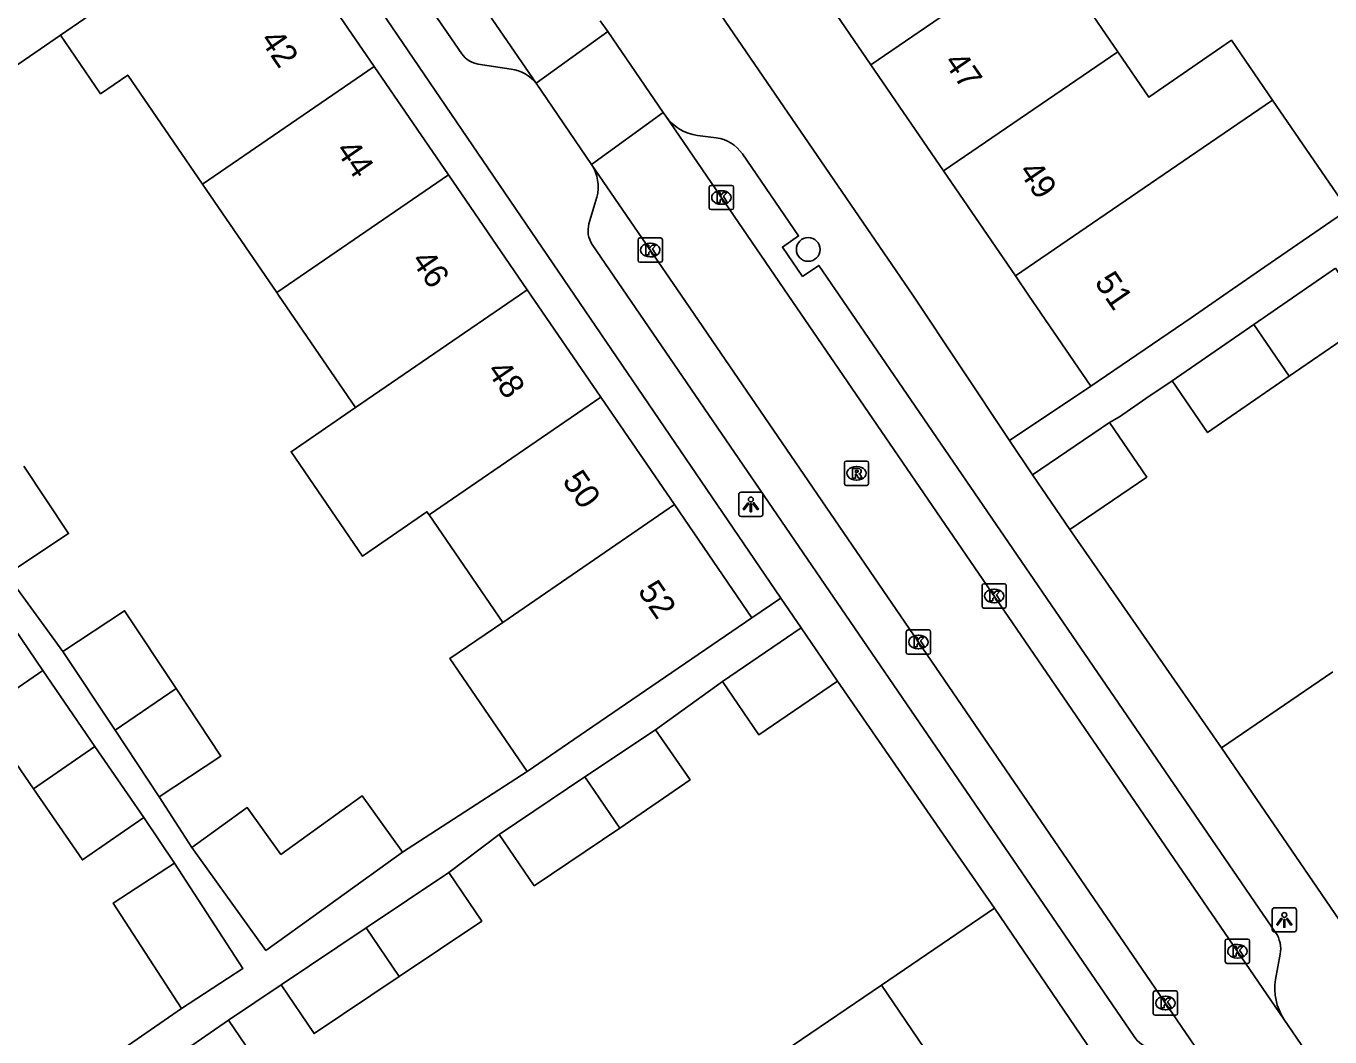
# Model space of a CAD drawing. Extents: x 157466 to 158888, y 383063 to 384677.
# Drawn here: x 158174.5 to 158228.2, y 383719.4 to 383761.1 of the extents above; entities that cross this region are included whole.
import ezdxf

# ---------------------------------------------------------------- set-up
doc = ezdxf.new("R2010")
doc.units = 0
for name, color, linetype in [('IMGEO_Boom', 7, 'Continuous'), ('IMGEO_Kolk', 7, 'Continuous'), ('IMGEO_Lichtpunt', 7, 'Continuous'), ('IMGEO_Muur', 7, 'Continuous'), ('IMGEO_Pand', 7, 'Continuous'), ('IMGEO_Pand_nummerreeks', 7, 'Continuous'), ('IMGEO_Rijbaan_lokaal_open', 7, 'Continuous'), ('IMGEO_Rioolput', 7, 'Continuous'), ('IMGEO_Voetpad_open', 7, 'Continuous')]:
    doc.layers.add(name, color=color, linetype=linetype)

msp = doc.modelspace()

# ---------------------------------------------------------------- linework, layer by layer
at = {"layer": 'IMGEO_Boom'}
msp.add_circle((158206.748, 383751.883), 0.489, dxfattribs=at)
at = {"layer": 'IMGEO_Kolk'}
for p, q in [((158202.669, 383753.595), (158202.669, 383754.447)), ((158202.744, 383754.521), (158203.596, 383754.521)), ((158203.157, 383754.301), (158203.182, 383754.301)), ((158203.67, 383754.447), (158203.67, 383753.595)), ((158203.18, 383753.741), (158203.155, 383753.741)), ((158203.596, 383753.521), (158202.744, 383753.521)), ((158199.737, 383751.428), (158199.737, 383752.28)), ((158199.812, 383752.354), (158200.664, 383752.354)), ((158200.225, 383752.134), (158200.25, 383752.134)), ((158200.738, 383752.28), (158200.738, 383751.428)), ((158200.248, 383751.574), (158200.223, 383751.574)), ((158200.664, 383751.354), (158199.812, 383751.354)), ((158213.984, 383738.11), (158214.836, 383738.11)), ((158213.909, 383737.184), (158213.909, 383738.036)), ((158214.397, 383737.89), (158214.422, 383737.89)), ((158214.91, 383738.036), (158214.91, 383737.184)), ((158214.836, 383737.11), (158213.984, 383737.11)), ((158214.42, 383737.33), (158214.395, 383737.33)), ((158210.788, 383735.283), (158210.788, 383736.135)), ((158210.863, 383736.209), (158211.715, 383736.209)), ((158211.276, 383735.989), (158211.301, 383735.989)), ((158211.789, 383736.135), (158211.789, 383735.283)), ((158211.299, 383735.429), (158211.274, 383735.429)), ((158211.715, 383735.209), (158210.863, 383735.209)), ((158223.932, 383722.549), (158223.932, 383723.401)), ((158224.007, 383723.475), (158224.859, 383723.475)), ((158224.42, 383723.255), (158224.445, 383723.255)), ((158224.933, 383723.401), (158224.933, 383722.549)), ((158224.859, 383722.475), (158224.007, 383722.475)), ((158224.443, 383722.695), (158224.418, 383722.695)), ((158220.967, 383720.413), (158220.967, 383721.265)), ((158221.042, 383721.339), (158221.894, 383721.339)), ((158221.455, 383721.119), (158221.48, 383721.119)), ((158221.968, 383721.265), (158221.968, 383720.413)), ((158221.894, 383720.339), (158221.042, 383720.339)), ((158221.478, 383720.559), (158221.453, 383720.559))]:
    msp.add_line(p, q, dxfattribs=at)
for points in [[(158202.669, 383753.595), (158202.669, 383754.447)], [(158202.744, 383754.521), (158203.596, 383754.521)], [(158202.99, 383754.221), (158203.113, 383754.221), (158203.113, 383754.07), (158203.243, 383754.221), (158203.407, 383754.221), (158203.261, 383754.07), (158203.414, 383753.821), (158203.262, 383753.821), (158203.177, 383753.985), (158203.113, 383753.918), (158203.113, 383753.821), (158202.99, 383753.821), (158202.99, 383754.221)], [(158203.67, 383754.447), (158203.67, 383753.595)], [(158203.596, 383753.521), (158202.744, 383753.521)], [(158199.737, 383751.428), (158199.737, 383752.28)], [(158199.812, 383752.354), (158200.664, 383752.354)], [(158200.058, 383752.054), (158200.181, 383752.054), (158200.181, 383751.903), (158200.311, 383752.054), (158200.475, 383752.054), (158200.329, 383751.903), (158200.482, 383751.654), (158200.33, 383751.654), (158200.245, 383751.818), (158200.181, 383751.751), (158200.181, 383751.654), (158200.058, 383751.654), (158200.058, 383752.054)], [(158200.738, 383752.28), (158200.738, 383751.428)], [(158200.664, 383751.354), (158199.812, 383751.354)], [(158213.984, 383738.11), (158214.836, 383738.11)], [(158213.909, 383737.184), (158213.909, 383738.036)], [(158214.23, 383737.81), (158214.353, 383737.81), (158214.353, 383737.659), (158214.483, 383737.81), (158214.647, 383737.81), (158214.501, 383737.659), (158214.654, 383737.41), (158214.502, 383737.41), (158214.417, 383737.574), (158214.353, 383737.507), (158214.353, 383737.41), (158214.23, 383737.41), (158214.23, 383737.81)], [(158214.91, 383738.036), (158214.91, 383737.184)], [(158214.836, 383737.11), (158213.984, 383737.11)], [(158210.788, 383735.283), (158210.788, 383736.135)], [(158210.863, 383736.209), (158211.715, 383736.209)], [(158211.109, 383735.909), (158211.232, 383735.909), (158211.232, 383735.758), (158211.362, 383735.909), (158211.526, 383735.909), (158211.38, 383735.758), (158211.533, 383735.509), (158211.381, 383735.509), (158211.296, 383735.673), (158211.232, 383735.606), (158211.232, 383735.509), (158211.109, 383735.509), (158211.109, 383735.909)], [(158211.789, 383736.135), (158211.789, 383735.283)], [(158211.715, 383735.209), (158210.863, 383735.209)], [(158223.932, 383722.549), (158223.932, 383723.401)], [(158224.007, 383723.475), (158224.859, 383723.475)], [(158224.253, 383723.175), (158224.376, 383723.175), (158224.376, 383723.024), (158224.506, 383723.175), (158224.67, 383723.175), (158224.524, 383723.024), (158224.677, 383722.775), (158224.525, 383722.775), (158224.44, 383722.939), (158224.376, 383722.872), (158224.376, 383722.775), (158224.253, 383722.775), (158224.253, 383723.175)], [(158224.933, 383723.401), (158224.933, 383722.549)], [(158224.859, 383722.475), (158224.007, 383722.475)], [(158220.967, 383720.413), (158220.967, 383721.265)], [(158221.042, 383721.339), (158221.894, 383721.339)], [(158221.288, 383721.039), (158221.411, 383721.039), (158221.411, 383720.888), (158221.541, 383721.039), (158221.705, 383721.039), (158221.559, 383720.888), (158221.712, 383720.639), (158221.56, 383720.639), (158221.475, 383720.803), (158221.411, 383720.736), (158221.411, 383720.639), (158221.288, 383720.639), (158221.288, 383721.039)], [(158221.968, 383721.265), (158221.968, 383720.413)], [(158221.894, 383720.339), (158221.042, 383720.339)]]:
    msp.add_lwpolyline(points, dxfattribs=at)
for centre, start, end in [((158202.746, 383754.445), 91.552, 178.448), ((158202.746, 383754.445), 91.552, 178.448), ((158203.594, 383754.445), 1.552, 88.448), ((158203.594, 383754.445), 1.552, 88.448), ((158202.746, 383753.597), 181.552, 268.448), ((158202.746, 383753.597), 181.552, 268.448), ((158203.594, 383753.597), 271.552, 358.448), ((158203.594, 383753.597), 271.552, 358.448), ((158199.814, 383752.278), 91.552, 178.448), ((158199.814, 383752.278), 91.552, 178.448), ((158200.662, 383752.278), 1.552, 88.448), ((158200.662, 383752.278), 1.552, 88.448), ((158199.814, 383751.43), 181.552, 268.448), ((158199.814, 383751.43), 181.552, 268.448), ((158200.662, 383751.43), 271.552, 358.448), ((158200.662, 383751.43), 271.552, 358.448), ((158213.986, 383738.034), 91.552, 178.448), ((158213.986, 383738.034), 91.552, 178.448), ((158214.834, 383738.034), 1.552, 88.448), ((158214.834, 383738.034), 1.552, 88.448), ((158213.986, 383737.186), 181.552, 268.448), ((158213.986, 383737.186), 181.552, 268.448), ((158214.834, 383737.186), 271.552, 358.448), ((158214.834, 383737.186), 271.552, 358.448), ((158210.865, 383736.133), 91.552, 178.448), ((158210.865, 383736.133), 91.552, 178.448), ((158211.713, 383736.133), 1.552, 88.448), ((158211.713, 383736.133), 1.552, 88.448), ((158210.865, 383735.285), 181.552, 268.448), ((158210.865, 383735.285), 181.552, 268.448), ((158211.713, 383735.285), 271.552, 358.448), ((158211.713, 383735.285), 271.552, 358.448), ((158224.009, 383723.399), 91.552, 178.448), ((158224.009, 383723.399), 91.552, 178.448), ((158224.857, 383723.399), 1.552, 88.448), ((158224.857, 383723.399), 1.552, 88.448), ((158224.009, 383722.551), 181.552, 268.448), ((158224.009, 383722.551), 181.552, 268.448), ((158224.857, 383722.551), 271.552, 358.448), ((158224.857, 383722.551), 271.552, 358.448), ((158221.044, 383721.263), 91.552, 178.448), ((158221.044, 383721.263), 91.552, 178.448), ((158221.892, 383721.263), 1.552, 88.448), ((158221.892, 383721.263), 1.552, 88.448), ((158221.044, 383720.415), 181.552, 268.448), ((158221.044, 383720.415), 181.552, 268.448), ((158221.892, 383720.415), 271.552, 358.448), ((158221.892, 383720.415), 271.552, 358.448)]:
    msp.add_arc(centre, 0.0765, start, end, dxfattribs=at)
for centre, major_axis, ratio, start_param, end_param in [((158203.156, 383754.021), (-0.387, 0.002), 0.722429, 4.712389, 7.853982), ((158203.181, 383754.021), (-0.39, 0.002), 0.717154, 1.570796, 4.712389), ((158200.224, 383751.854), (-0.387, 0.002), 0.722429, 4.712389, 7.853982), ((158200.249, 383751.854), (-0.39, 0.002), 0.717154, 1.570796, 4.712389), ((158214.396, 383737.61), (-0.387, 0.002), 0.722429, 4.712389, 7.853982), ((158214.421, 383737.61), (-0.39, 0.002), 0.717154, 1.570796, 4.712389), ((158211.275, 383735.709), (-0.387, 0.002), 0.722429, 4.712389, 7.853982), ((158211.3, 383735.709), (-0.39, 0.002), 0.717154, 1.570796, 4.712389), ((158224.419, 383722.975), (-0.387, 0.002), 0.722429, 4.712389, 7.853982), ((158224.444, 383722.975), (-0.39, 0.002), 0.717154, 1.570796, 4.712389), ((158221.454, 383720.839), (-0.387, 0.002), 0.722429, 4.712389, 7.853982), ((158221.479, 383720.839), (-0.39, 0.002), 0.717154, 1.570796, 4.712389)]:
    msp.add_ellipse(centre, major_axis=major_axis, ratio=ratio, start_param=start_param, end_param=end_param, dxfattribs=at)
at = {"layer": 'IMGEO_Lichtpunt'}
for p, q in [((158204.788, 383741.88), (158203.98, 383741.88)), ((158204.788, 383741.88), (158203.98, 383741.88)), ((158203.886, 383741.785), (158203.886, 383740.978)), ((158203.886, 383741.785), (158203.886, 383740.978)), ((158204.882, 383740.978), (158204.882, 383741.785)), ((158204.882, 383740.978), (158204.882, 383741.785)), ((158203.98, 383740.884), (158204.788, 383740.884)), ((158203.98, 383740.884), (158204.788, 383740.884)), ((158225.866, 383724.672), (158225.866, 383723.865)), ((158225.866, 383724.672), (158225.866, 383723.865)), ((158226.768, 383724.767), (158225.96, 383724.767)), ((158226.768, 383724.767), (158225.96, 383724.767)), ((158226.862, 383723.865), (158226.862, 383724.672)), ((158226.862, 383723.865), (158226.862, 383724.672)), ((158225.96, 383723.771), (158226.768, 383723.771)), ((158225.96, 383723.771), (158226.768, 383723.771))]:
    msp.add_line(p, q, dxfattribs=at)
for points in [[(158204.26, 383741.449), (158204.299, 383741.421), (158204.111, 383741.159), (158204.073, 383741.186), (158204.26, 383741.449)], [(158204.362, 383741.401), (158204.409, 383741.401), (158204.409, 383741.079), (158204.362, 383741.079), (158204.362, 383741.401)], [(158204.472, 383741.421), (158204.51, 383741.448), (158204.697, 383741.186), (158204.658, 383741.158), (158204.472, 383741.421)], [(158226.24, 383724.336), (158226.279, 383724.308), (158226.091, 383724.046), (158226.053, 383724.073), (158226.24, 383724.336)], [(158226.342, 383724.288), (158226.389, 383724.288), (158226.389, 383723.966), (158226.342, 383723.966), (158226.342, 383724.288)], [(158226.452, 383724.308), (158226.49, 383724.335), (158226.677, 383724.073), (158226.638, 383724.045), (158226.452, 383724.308)]]:
    msp.add_lwpolyline(points, dxfattribs=at)
for centre in [(158204.385, 383741.583), (158226.365, 383724.47)]:
    msp.add_circle(centre, 0.0994, dxfattribs=at)
for centre, start, end in [((158203.98, 383741.785), 90, 180), ((158203.98, 383741.785), 90, 180), ((158204.788, 383741.785), 0, 90), ((158204.788, 383741.785), 0, 90), ((158203.98, 383740.978), 180, 270), ((158203.98, 383740.978), 180, 270), ((158204.788, 383740.978), 270, 0), ((158204.788, 383740.978), 270, 360), ((158225.96, 383724.672), 90, 180), ((158225.96, 383724.672), 90, 180), ((158226.768, 383724.672), 0, 90), ((158226.768, 383724.672), 0, 90), ((158225.96, 383723.865), 180, 270), ((158225.96, 383723.865), 180, 270), ((158226.768, 383723.865), 270, 0), ((158226.768, 383723.865), 270, 360)]:
    msp.add_arc(centre, 0.0946, start, end, dxfattribs=at)
at = {"layer": 'IMGEO_Muur'}
for points in [[(158222.063, 383733.823), (158223.783, 383731.353)], [(158212.709, 383727.225), (158214.422, 383724.75)]]:
    msp.add_lwpolyline(points, dxfattribs=at)
at = {"layer": 'IMGEO_Pand'}
for points in [[(158216.508, 383764.396), (158209.334, 383759.486)], [(158219.501, 383760.026), (158216.508, 383764.396)], [(158175.939, 383760.709), (158180.833, 383764.065)], [(158180.833, 383764.065), (158182.46, 383761.691), (158185.753, 383763.949), (158188.863, 383759.413)], [(158209.334, 383759.486), (158206.199, 383764.067)], [(158175.939, 383760.709), (158177.586, 383758.297), (158178.707, 383759.066), (158181.791, 383754.566)], [(158219.501, 383760.026), (158220.781, 383758.158), (158224.188, 383760.497), (158225.877, 383758.036)], [(158212.326, 383755.115), (158219.501, 383760.026)], [(158188.863, 383759.413), (158181.791, 383754.566)], [(158188.863, 383759.413), (158191.92, 383754.953)], [(158212.326, 383755.115), (158209.334, 383759.486)], [(158225.877, 383758.036), (158222.464, 383755.701), (158215.286, 383750.789)], [(158228.983, 383753.512), (158225.877, 383758.036)], [(158184.848, 383750.106), (158191.92, 383754.953)], [(158191.92, 383754.953), (158195.167, 383750.218)], [(158215.286, 383750.789), (158212.326, 383755.115)], [(158181.791, 383754.566), (158184.848, 383750.106)], [(158228.983, 383753.512), (158225.569, 383751.168), (158223.877, 383750), (158222.525, 383749.067), (158218.397, 383746.244)], [(158225.108, 383748.791), (158228.476, 383751.106)], [(158226.568, 383746.655), (158229.936, 383748.97), (158228.476, 383751.106)], [(158218.397, 383746.244), (158215.826, 383750), (158215.286, 383750.789)], [(158184.848, 383750.106), (158184.921, 383750), (158188.094, 383745.37)], [(158195.167, 383750.218), (158194.849, 383750), (158188.094, 383745.37)], [(158195.167, 383750.218), (158195.316, 383750), (158198.201, 383745.792)], [(158221.742, 383746.476), (158225.108, 383748.791)], [(158226.568, 383746.655), (158225.108, 383748.791)], [(158221.742, 383746.476), (158223.202, 383744.341), (158226.568, 383746.655)], [(158198.201, 383745.792), (158191.128, 383740.944)], [(158198.201, 383745.792), (158201.232, 383741.371)], [(158188.094, 383745.37), (158185.436, 383743.548), (158188.379, 383739.254), (158191.037, 383741.076), (158191.128, 383740.944)], [(158215.989, 383742.592), (158219.158, 383744.755)], [(158219.158, 383744.755), (158220.694, 383742.504), (158217.525, 383740.341)], [(158173.727, 383738.491), (158176.267, 383740.175), (158174.421, 383742.96)], [(158217.525, 383740.341), (158215.989, 383742.592)], [(158194.158, 383736.522), (158201.232, 383741.371)], [(158201.232, 383741.371), (158204.427, 383736.711)], [(158191.128, 383740.944), (158194.158, 383736.522)], [(158180.702, 383733.797), (158178.578, 383737), (158176.038, 383735.315)], [(158194.158, 383736.522), (158191.984, 383735.035), (158195.169, 383730.379)], [(158195.169, 383730.379), (158197.347, 383731.869), (158200.3, 383733.889), (158204.427, 383736.711)], [(158206.451, 383736.296), (158203.212, 383734.083)], [(158206.451, 383736.296), (158207.95, 383734.103)], [(158176.038, 383735.315), (158178.187, 383732.074)], [(158174.823, 383729.666), (158172.674, 383732.789), (158175.207, 383734.532)], [(158177.358, 383731.405), (158175.207, 383734.532)], [(158228.359, 383734.479), (158223.783, 383731.353)], [(158178.187, 383732.074), (158180.702, 383733.797)], [(158180.007, 383729.329), (158182.547, 383731.013), (158180.702, 383733.797)], [(158203.212, 383734.083), (158204.711, 383731.89), (158207.95, 383734.103)], [(158178.187, 383732.074), (158180.007, 383729.329)], [(158200.45, 383732.101), (158197.547, 383730.153)], [(158198.986, 383728.037), (158201.878, 383730.036), (158200.45, 383732.101)], [(158177.358, 383731.405), (158174.823, 383729.666)], [(158179.371, 383728.48), (158177.358, 383731.405)], [(158228.626, 383724.267), (158223.783, 383731.353)], [(158197.547, 383730.153), (158194.017, 383727.784)], [(158198.986, 383728.037), (158197.547, 383730.153)], [(158174.823, 383729.666), (158176.838, 383726.737), (158179.371, 383728.48)], [(158190.035, 383727.055), (158189.974, 383727.139), (158188.37, 383729.37), (158185.021, 383726.963), (158183.634, 383728.892), (158181.352, 383727.251)], [(158194.017, 383727.784), (158195.457, 383725.669), (158198.986, 383728.037)], [(158181.352, 383727.251), (158184.404, 383723.006), (158186.686, 383724.647), (158190.035, 383727.055)], [(158180.635, 383726.599), (158178.109, 383724.961), (158180.923, 383720.622)], [(158180.923, 383720.622), (158183.448, 383722.259), (158180.635, 383726.599)], [(158191.935, 383726.214), (158188.539, 383723.935)], [(158189.897, 383721.938), (158193.293, 383724.217), (158191.935, 383726.214)], [(158214.422, 383724.75), (158209.762, 383721.581)], [(158214.422, 383724.75), (158219.171, 383717.767)], [(158188.539, 383723.935), (158185.024, 383721.588)], [(158188.539, 383723.935), (158189.897, 383721.938)], [(158185.024, 383721.588), (158186.387, 383719.582), (158189.897, 383721.938)], [(158209.762, 383721.581), (158205.394, 383718.611)], [(158214.51, 383714.598), (158209.762, 383721.581)], [(158182.857, 383720.133), (158179.486, 383717.803)], [(158180.916, 383715.7), (158184.286, 383718.03), (158182.857, 383720.133)]]:
    msp.add_lwpolyline(points, dxfattribs=at)
at = {"layer": 'IMGEO_Rijbaan_lokaal_open'}
for points in [[(158195.535, 383758.724), (158190.126, 383766.615)], [(158198.181, 383761.303), (158198.486, 383760.859)], [(158198.486, 383760.859), (158195.535, 383758.724)], [(158198.486, 383760.859), (158200.771, 383757.522)], [(158197.821, 383755.384), (158195.535, 383758.724)], [(158197.821, 383755.384), (158200.771, 383757.522)], [(158200.771, 383757.522), (158200.878, 383757.366)], [(158200.878, 383757.366), (158205.923, 383750), (158226.348, 383720.178)], [(158223.574, 383717.762), (158201.507, 383750), (158197.821, 383755.384)], [(158226.348, 383720.178), (158227.982, 383717.792)]]:
    msp.add_lwpolyline(points, dxfattribs=at)
at = {"layer": 'IMGEO_Rioolput'}
for p, q in [((158208.236, 383742.236), (158208.236, 383743.088)), ((158208.311, 383743.162), (158209.163, 383743.162)), ((158208.724, 383742.942), (158208.749, 383742.942)), ((158209.237, 383743.088), (158209.237, 383742.236)), ((158208.747, 383742.382), (158208.722, 383742.382)), ((158209.163, 383742.162), (158208.311, 383742.162))]:
    msp.add_line(p, q, dxfattribs=at)
for points in [[(158208.236, 383742.236), (158208.236, 383743.088)], [(158208.311, 383743.162), (158209.163, 383743.162)], [(158209.237, 383743.088), (158209.237, 383742.236)], [(158208.825, 383742.86), (158208.573, 383742.862), (158208.573, 383742.462)], [(158208.573, 383742.462), (158208.697, 383742.462), (158208.697, 383742.624), (158208.708, 383742.624)], [(158208.751, 383742.781), (158208.697, 383742.781), (158208.697, 383742.7)], [(158208.697, 383742.7), (158208.749, 383742.7)], [(158208.755, 383742.595), (158208.826, 383742.462), (158208.966, 383742.462), (158208.901, 383742.588)], [(158209.163, 383742.162), (158208.311, 383742.162)]]:
    msp.add_lwpolyline(points, dxfattribs=at)
for centre, radius, start, end in [((158208.313, 383743.086), 0.0765, 91.552, 178.448), ((158208.313, 383743.086), 0.0765, 91.552, 178.448), ((158209.161, 383743.086), 0.0765, 1.552, 88.448), ((158209.161, 383743.086), 0.0765, 1.552, 88.448), ((158208.707, 383742.571), 0.0533, 26.0293, 88.6989), ((158208.733, 383742.889), 0.19, 274.7715, 282.9687), ((158208.757, 383742.685), 0.0964, 77.0061, 93.1865), ((158208.771, 383742.742), 0.0378, 276.6634, 79.6772), ((158208.824, 383742.75), 0.109, 350.3612, 89.416), ((158208.822, 383742.75), 0.112, 277.5842, 350.9817), ((158208.806, 383742.535), 0.108, 29.5134, 73.7905), ((158208.313, 383742.238), 0.0765, 181.552, 268.448), ((158208.313, 383742.238), 0.0765, 181.552, 268.448), ((158209.161, 383742.238), 0.0765, 271.552, 358.448), ((158209.161, 383742.238), 0.0765, 271.552, 358.448)]:
    msp.add_arc(centre, radius, start, end, dxfattribs=at)
for centre, major_axis, ratio, start_param, end_param in [((158208.723, 383742.662), (-0.387, 0.002), 0.722429, 4.712389, 7.853982), ((158208.748, 383742.662), (-0.39, 0.002), 0.717154, 1.570796, 4.712389)]:
    msp.add_ellipse(centre, major_axis=major_axis, ratio=ratio, start_param=start_param, end_param=end_param, dxfattribs=at)
at = {"layer": 'IMGEO_Voetpad_open'}
for points in [[(158182.895, 383791.111), (158211.057, 383750), (158215.044, 383744.012)], [(158185.398, 383767.212), (158197.119, 383750), (158205.617, 383737.521)], [(158192.476, 383759.938), (158190.295, 383763.124)], [(158169.708, 383756.443), (158175.939, 383760.709)], [(158194.513, 383759.311), (158193.154, 383759.513)], [(158202.184, 383756.58), (158202.957, 383756.479)], [(158204.036, 383755.818), (158206.352, 383752.436), (158205.684, 383751.978), (158206.513, 383750.768), (158207.181, 383751.226), (158208.021, 383750), (158226.006, 383723.745)], [(158197.714, 383752.937), (158198.036, 383754.029)], [(158220.175, 383719.459), (158199.279, 383750), (158197.849, 383752.09)], [(158215.044, 383744.012), (158218.397, 383746.244)], [(158219.158, 383744.755), (158219.58, 383744.988), (158220.666, 383745.736), (158221.742, 383746.476)], [(158215.989, 383742.592), (158215.044, 383744.012)], [(158223.783, 383731.353), (158222.063, 383733.823), (158217.525, 383740.341)], [(158173.727, 383738.491), (158176.038, 383735.315)], [(158175.207, 383734.532), (158173.142, 383737.56)], [(158204.427, 383736.711), (158205.617, 383737.521)], [(158205.617, 383737.521), (158206.451, 383736.296)], [(158203.212, 383734.083), (158200.45, 383732.101)], [(158207.95, 383734.103), (158212.709, 383727.225), (158214.422, 383724.75)], [(158190.035, 383727.055), (158195.169, 383730.379)], [(158180.007, 383729.329), (158181.352, 383727.251)], [(158180.635, 383726.599), (158179.371, 383728.48)], [(158194.017, 383727.784), (158191.935, 383726.214)], [(158226.196, 383722.85), (158226.005, 383721.81)], [(158185.024, 383721.588), (158182.857, 383720.133)], [(158170.7, 383713.558), (158180.923, 383720.622)]]:
    msp.add_lwpolyline(points, dxfattribs=at)
for centre, radius, start, end in [((158193.304, 383760.506), 1.005, 214.4507, 261.3867), ((158194.267, 383757.699), 1.631, 38.943, 81.314), ((158202.433, 383758.472), 1.908, 215.4182, 262.4996), ((158202.759, 383754.945), 1.547, 34.3636, 82.6528), ((158196.389, 383754.462), 1.703, 345.2628, 32.7693), ((158198.672, 383752.655), 0.999, 163.6293, 214.4826), ((158225.007, 383723.065), 1.209, 349.7442, 34.2266), ((158228.284, 383721.437), 2.309, 170.6991, 213.0393), ((158221.167, 383720.139), 1.203, 214.4218, 256.3899)]:
    msp.add_arc(centre, radius, start, end, dxfattribs=at)

# ---------------------------------------------------------------- texts
at = {"layer": 'IMGEO_Pand_nummerreeks'}
for s, rotation, p in [('42', 304.434, (158184.134, 383760.508)), ('47', 304.3867, (158212.313, 383759.596)), ('44', 304.434, (158187.249, 383755.967)), ('49', 304.3867, (158215.392, 383755.097)), ('46', 304.434, (158190.361, 383751.427)), ('51', 304.3826, (158218.52, 383750.529)), ('48', 304.4346, (158193.475, 383746.884)), ('50', 304.434, (158196.588, 383742.345)), ('52', 304.434, (158199.696, 383737.81))]:
    msp.add_text(s, height=1, rotation=rotation, dxfattribs=at).set_placement(p)

doc.saveas('drawing.dxf')
